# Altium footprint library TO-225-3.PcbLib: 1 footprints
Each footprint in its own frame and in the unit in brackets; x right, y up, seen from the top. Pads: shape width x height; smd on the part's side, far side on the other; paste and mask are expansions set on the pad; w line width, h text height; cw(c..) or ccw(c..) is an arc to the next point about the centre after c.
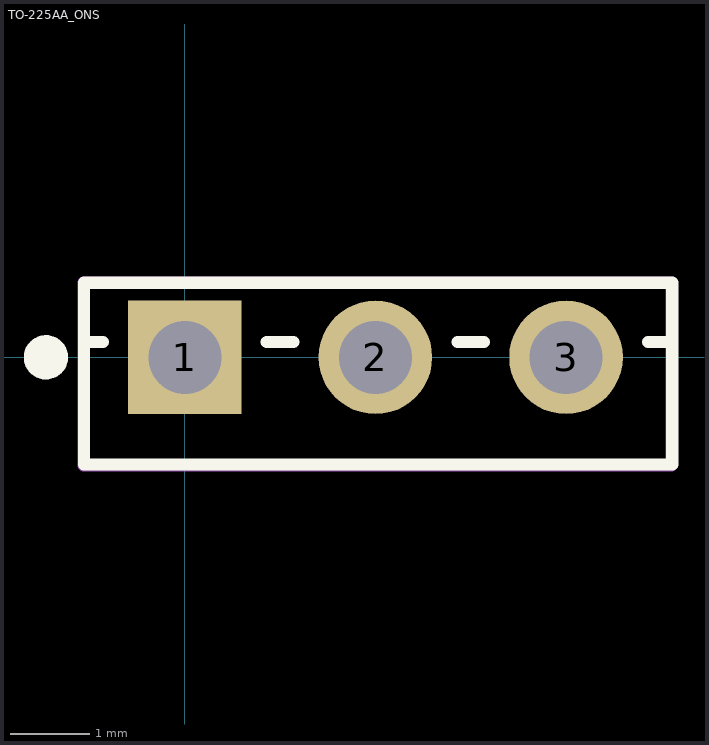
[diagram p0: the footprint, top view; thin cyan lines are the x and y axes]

## TO-225AA_ONS [mil]
pads (3):
  rect 56x56 hole 36: 1(0,0)
  round 56 hole 36: 2(94,0) 3(188,0)
Top Overlay:
  circle w11.81: c-68.5,0 r5
  lines w6: -49.69,7.5 -40.41,7.5 ; 40.41,7.5 53.59,7.5 ; 134.41,7.5 147.59,7.5 ; 228.41,7.5 239.19,7.5 ; -49.67,-52.9 240.35,-52.9 240.35,36.75 -49.67,36.75 -49.67,-52.9
Mechanical 15:
  lines w6: -50,-53.3 -50,36.84 240,36.84 240,-53.3 -50,-53.3
3D body "TO-225-3.STEP": height 543.31, standoff -457.09, extent -52.64,-55.28 242.64,40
